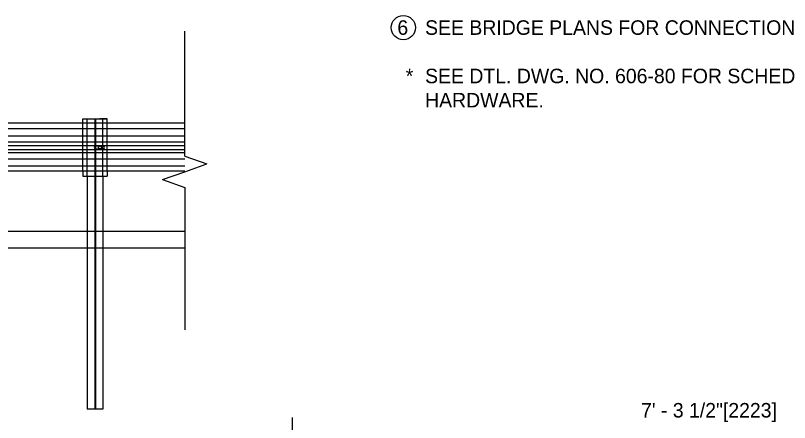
# Model space of a CAD drawing. Extents: x 49991 to 50160, y 49948 to 50051.
# Drawn here: x 50010.973 to 50014.17, y 49994.263 to 49995.945 of the extents above; entities that cross this region are included whole.
import ezdxf

# ---------------------------------------------------------------- set-up
doc = ezdxf.new("R2010")
doc.units = 0
for name, color, linetype in [('Level 1', 7, 'Continuous'), ('Level 2', 7, 'Continuous'), ('Level 3', 7, 'Continuous'), ('Level 4', 7, 'Continuous'), ('Level 6', 7, 'Continuous')]:
    doc.layers.add(name, color=color, linetype=linetype)

msp = doc.modelspace()

# ---------------------------------------------------------------- linework, layer by layer
at = {"layer": 'Level 1'}
for p, q in [((50004.3866, 49995.502), (50011.6716, 49995.5015)), ((50011.2508, 49995.5182), (50011.3508, 49995.5182)), ((50011.2508, 49995.5015), (50011.2508, 49995.5182)), ((50011.2685, 49995.5182), (50011.3341, 49995.5182)), ((50011.3508, 49995.5182), (50011.3216, 49995.5182)), ((50011.3508, 49995.5015), (50011.3508, 49995.5182)), ((50004.5497, 49995.4777), (50011.6716, 49995.4777)), ((50004.5497, 49995.4486), (50011.6716, 49995.448)), ((50004.5497, 49995.4215), (50011.6716, 49995.4225)), ((50005.0854, 49995.409), (50011.6716, 49995.4068)), ((50011.3049, 49995.4058), (50011.3345, 49995.4058)), ((50011.3345, 49995.3927), (50011.3049, 49995.3927)), ((50011.6716, 49995.3902), (50005.5897, 49995.3903)), ((50011.6716, 49995.3773), (50005.5897, 49995.3773)), ((50011.6716, 49995.3504), (50005.5897, 49995.3504)), ((50011.6716, 49995.3214), (50005.5897, 49995.3214)), ((50011.6716, 49995.3012), (50005.5897, 49995.3012)), ((50011.2508, 49995.3012), (50011.2508, 49995.2807)), ((50011.3508, 49995.3012), (50011.3508, 49995.2807)), ((50011.2508, 49995.2807), (50011.3508, 49995.2807)), ((50011.2685, 49995.2807), (50011.2685, 49995.0515)), ((50011.3341, 49995.2807), (50011.3341, 49995.0515)), ((50011.6716, 49995.0515), (50000.8175, 49995.052)), ((49999.8238, 49994.9854), (50011.6716, 49994.9849))]:
    msp.add_line(p, q, dxfattribs=at)
msp.add_circle((50011.3216, 49995.3995), 0.00625, dxfattribs=at)
for centre, start, end in [((50011.3049, 49995.3992), 90, 270), ((50011.3345, 49995.3992), 270, 90)]:
    msp.add_arc(centre, 0.00656, start, end, dxfattribs=at)
at = {"layer": 'Level 2'}
msp.add_circle((50012.5746, 49995.8948), 0.05, dxfattribs=at)
at = {"layer": 'Level 3'}
msp.add_line((50012.1168, 49993.5214), (50012.1168, 49994.2833), dxfattribs=at)
at = {"layer": 'Level 4'}
for p, q in [((50011.2508, 49995.3012), (50011.2508, 49995.5015)), ((50011.2685, 49995.2807), (50011.2685, 49995.5182)), ((50011.2999, 49995.5182), (50011.2999, 49994.3182)), ((50011.3027, 49995.5182), (50011.3027, 49994.3182)), ((50011.3341, 49995.2807), (50011.3341, 49995.5182)), ((50011.3508, 49995.3012), (50011.3508, 49995.5015)), ((50011.2685, 49995.0515), (50011.2685, 49994.3182)), ((50011.3341, 49995.0515), (50011.3341, 49994.3182)), ((50011.3341, 49994.3182), (50011.2685, 49994.3182))]:
    msp.add_line(p, q, dxfattribs=at)
at = {"layer": 'Level 6'}
for p, q in [((50011.6716, 49995.3638), (50011.6716, 49995.88)), ((50011.6716, 49995.3638), (50011.763, 49995.3314)), ((50011.6716, 49995.299), (50011.763, 49995.3314)), ((50011.5802, 49995.2666), (50011.6716, 49995.299)), ((50011.5802, 49995.2666), (50011.6716, 49995.2342)), ((50011.6716, 49995.2342), (50011.6716, 49994.6459))]:
    msp.add_line(p, q, dxfattribs=at)

# ---------------------------------------------------------------- texts
at = {"layer": 'Level 2'}
for s, p in [('6', (50012.5501, 49995.8648)), ('SEE BRIDGE PLANS FOR CONNECTION DETAILS AND BOLT LOCATIONS.', (50012.6646, 49995.8648)), ('*', (50012.5848, 49995.6648)), ('SEE DTL. DWG. NO. 606-80 FOR SCHEDULE OF GUARDRAIL ', (50012.6646, 49995.6648)), ('HARDWARE.', (50012.6646, 49995.5648)), ('7\' - 3 1/2"[2223]', (50013.5565, 49994.2833))]:
    msp.add_text(s, height=0.06, dxfattribs=at).set_placement(p)

doc.saveas('drawing.dxf')
